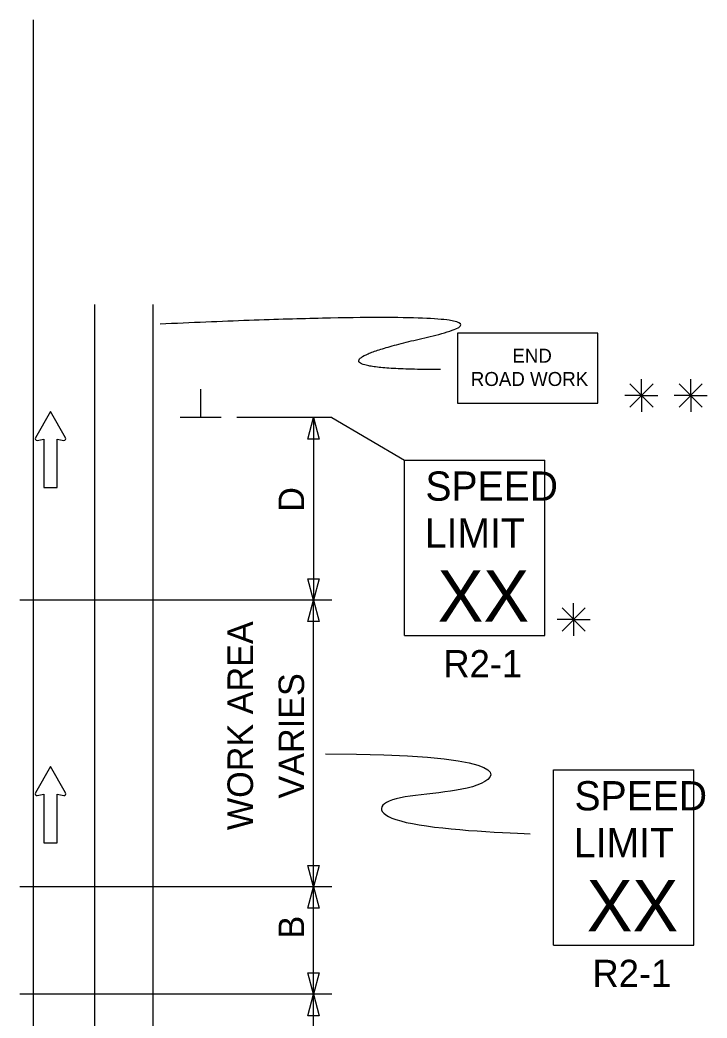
# Model space of a CAD drawing. Extents: x 16725 to 18479, y 5932 to 7023.
# Drawn here: x 16950.3 to 17138.5, y 6732.2 to 7005.6 of the extents above; entities that cross this region are included whole.
import ezdxf

# ---------------------------------------------------------------- set-up
doc = ezdxf.new("R2010")
doc.units = 0
for name, color, linetype in [('ALI_LEGAL_EX', 7, 'Continuous'), ('MT_SCRATCH_LEVEL_E', 7, 'Continuous'), ('PAVT_EDGE_EX', 7, 'Continuous'), ('TRAFFIC_SIGNS_PR', 7, 'Continuous'), ('TYPICAL_TEXT_DIMEN_PR', 7, 'Continuous')]:
    doc.layers.add(name, color=color, linetype=linetype)

msp = doc.modelspace()

# ---------------------------------------------------------------- linework, layer by layer
at = {"layer": 'ALI_LEGAL_EX'}
msp.add_line((16953.88, 7005.57), (16953.88, 6176.39), dxfattribs=at)
msp.add_line((16953.88, 7005.57), (16953.88, 6176.39), dxfattribs=at)
at = {"layer": 'MT_SCRATCH_LEVEL_E'}
for p, q in [((16958.65, 6898.33), (16954.54, 6891.09)), ((16962.8, 6891.09), (16958.65, 6898.33)), ((16955.02, 6890.41), (16956.8, 6890.72)), ((16956.8, 6890.72), (16956.8, 6877.46)), ((16960.54, 6877.46), (16960.54, 6890.72)), ((16960.54, 6890.72), (16962.32, 6890.41)), ((16956.8, 6877.46), (16960.54, 6877.46)), ((16958.65, 6801.06), (16954.54, 6793.82)), ((16962.8, 6793.82), (16958.65, 6801.06)), ((16955.02, 6793.13), (16956.8, 6793.45)), ((16956.8, 6793.45), (16956.8, 6780.19)), ((16960.54, 6780.19), (16960.54, 6793.45)), ((16960.54, 6793.45), (16962.32, 6793.13)), ((16956.8, 6780.19), (16960.54, 6780.19))]:
    msp.add_line(p, q, dxfattribs=at)
for centre, start, end in [((16954.95, 6890.87), 150.4248, 279.9638), ((16962.39, 6890.87), 260.0362, 29.7731), ((16954.95, 6793.59), 150.4248, 279.9638), ((16962.39, 6793.59), 260.0362, 29.7731)]:
    msp.add_arc(centre, 0.463, start, end, dxfattribs=at)
at = {"layer": 'PAVT_EDGE_EX'}
for p, q in [((16970.69, 6927.61), (16970.69, 6189.52)), ((16986.69, 6927.61), (16986.69, 6189.52))]:
    msp.add_line(p, q, dxfattribs=at)
at = {"layer": 'TRAFFIC_SIGNS_PR'}
for p, q in [((17055.59, 6885.03), (17094.03, 6885.03)), ((17055.59, 6836.97), (17055.59, 6885.03)), ((17094.03, 6836.97), (17094.03, 6885.03)), ((17055.59, 6836.97), (17094.03, 6836.97)), ((17096.43, 6800.2), (17134.88, 6800.2)), ((17096.43, 6752.14), (17096.43, 6800.2)), ((17134.88, 6752.14), (17134.88, 6800.2)), ((17096.43, 6752.14), (17134.88, 6752.14))]:
    msp.add_line(p, q, dxfattribs=at)
msp.add_lwpolyline([(17070.18, 6900.57), (17108.58, 6900.57), (17108.58, 6919.77), (17070.18, 6919.77)], close=True, dxfattribs=at)
msp.add_open_spline([(17065.47, 6909.8), (17022.96, 6909.8), (17099.47, 6927.21), (16988.69, 6922.27)], degree=2, dxfattribs=at)
at = {"layer": 'TYPICAL_TEXT_DIMEN_PR'}
for p, q in [((17120.52, 6902.69), (17120.52, 6907.15)), ((17134.03, 6902.69), (17134.03, 6907.15)), ((16999.82, 6896.64), (16999.82, 6904.42)), ((17117.33, 6905.88), (17123.71, 6899.5)), ((17123.71, 6905.88), (17117.33, 6899.5)), ((17130.84, 6905.88), (17137.21, 6899.5)), ((17137.21, 6905.88), (17130.84, 6899.5)), ((17120.52, 6902.69), (17115.99, 6902.69)), ((17120.52, 6902.69), (17123.71, 6902.69)), ((17120.52, 6902.69), (17125, 6902.69)), ((17120.52, 6902.69), (17120.52, 6898.19)), ((17134.03, 6902.69), (17129.49, 6902.69)), ((17134.03, 6902.69), (17137.21, 6902.69)), ((17134.03, 6902.69), (17138.5, 6902.69)), ((17134.03, 6902.69), (17134.03, 6898.19)), ((17005.44, 6896.64), (16994.19, 6896.64)), ((17035.69, 6896.64), (17009.69, 6896.64)), ((17029.12, 6890.77), (17030.69, 6896.64)), ((17030.69, 6896.64), (17030.69, 6846.64)), ((17030.69, 6896.64), (17032.26, 6890.77)), ((17035.69, 6896.64), (17055.59, 6885.03)), ((17030.69, 6890.77), (17029.12, 6890.77)), ((17032.26, 6890.77), (17030.69, 6890.77)), ((17030.69, 6846.64), (17029.12, 6852.5)), ((17029.12, 6852.5), (17030.69, 6852.5)), ((17030.69, 6852.5), (17032.26, 6852.5)), ((17032.26, 6852.5), (17030.69, 6846.64)), ((17035.69, 6846.64), (16950.31, 6846.64)), ((17029.12, 6840.77), (17030.69, 6846.64)), ((17030.69, 6768.1), (17030.69, 6846.64)), ((17030.69, 6846.64), (17032.26, 6840.77)), ((17098.79, 6844.52), (17105.16, 6838.14)), ((17105.16, 6844.52), (17098.79, 6838.14)), ((17101.97, 6841.33), (17101.97, 6845.79)), ((17030.69, 6840.77), (17029.12, 6840.77)), ((17032.26, 6840.77), (17030.69, 6840.77)), ((17101.97, 6841.33), (17097.44, 6841.33)), ((17101.97, 6841.33), (17105.16, 6841.33)), ((17101.97, 6841.33), (17106.45, 6841.33)), ((17101.97, 6841.33), (17101.97, 6836.83)), ((17030.69, 6768.1), (17029.12, 6773.96)), ((17029.12, 6773.96), (17030.69, 6773.96)), ((17030.69, 6773.96), (17032.26, 6773.96)), ((17032.26, 6773.96), (17030.69, 6768.1)), ((17035.69, 6768.1), (16950.31, 6768.1)), ((17029.12, 6762.24), (17030.69, 6768.1)), ((17030.69, 6738.67), (17030.69, 6768.1)), ((17030.69, 6768.1), (17032.26, 6762.24)), ((17030.69, 6762.24), (17029.12, 6762.24)), ((17032.26, 6762.24), (17030.69, 6762.24)), ((17030.69, 6738.67), (17029.12, 6744.53)), ((17029.12, 6744.53), (17030.69, 6744.53)), ((17030.69, 6744.53), (17032.26, 6744.53)), ((17032.26, 6744.53), (17030.69, 6738.67)), ((17035.69, 6738.67), (16950.31, 6738.67)), ((17029.12, 6732.81), (17030.69, 6738.67)), ((17030.69, 6708.11), (17030.69, 6738.67)), ((17030.69, 6738.67), (17032.26, 6732.81)), ((17030.69, 6732.81), (17029.12, 6732.81)), ((17032.26, 6732.81), (17030.69, 6732.81))]:
    msp.add_line(p, q, dxfattribs=at)
msp.add_open_spline([(17034, 6804.5), (17082.47, 6804.5), (17082.47, 6793.75), (17047.55, 6793.75), (17047.55, 6784.7), (17081.76, 6782.94), (17090.05, 6782.65)], degree=3, dxfattribs=at)

# ---------------------------------------------------------------- texts
at = {"layer": 'TRAFFIC_SIGNS_PR'}
for s, height, p in [('END', 3.831, (17085.18, 6911.69)), ('ROAD WORK', 3.831, (17073.79, 6905.31)), ('SPEED', 8.01, (17061.36, 6873.88)), ('LIMIT', 8.01, (17061.2, 6861.06)), ('XX', 14.048, (17064.71, 6840.73)), ('R2-1', 7.449, (17066.28, 6825.52)), ('SPEED', 8.01, (17102.2, 6789.05)), ('LIMIT', 8.01, (17102.04, 6776.23)), ('XX', 14.048, (17105.55, 6755.9)), ('R2-1', 7.449, (17107.12, 6740.68))]:
    msp.add_text(s, height=height, dxfattribs=at).set_placement(p)
at = {"layer": 'TYPICAL_TEXT_DIMEN_PR'}
for s, p in [('D', (17028.14, 6870.85)), ('WORK AREA', (17014.14, 6783.65)), ('VARIES', (17028.14, 6792.29)), ('B', (17028.14, 6753.94))]:
    msp.add_text(s, height=7, rotation=90, dxfattribs=at).set_placement(p)

doc.saveas('drawing.dxf')
